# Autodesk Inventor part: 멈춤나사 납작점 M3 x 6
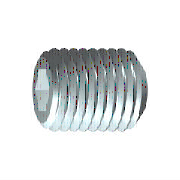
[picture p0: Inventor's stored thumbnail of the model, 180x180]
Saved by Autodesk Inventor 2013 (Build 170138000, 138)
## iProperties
IsCustomPart: 1
Created: 2012-02
Part Number: 멈춤나사 납작점 M3 x 6
Material: 강철, 연강
Description: 6각 소켓 머리 없는 멈춤 나사
Document SubType Name: Modeling
Standard: KS B 1028
Designer: mduedu
Standards Organization: KS
Language: ko-KR
Size Designation: 납작점M3x6
Categories: <MemberInstance><Categories><Category DisplayName="조임쇠" InternalName="e4da775c-781d-43d5-af7c-5136215cf5a6" Mnemonic="FSTN"><Category DisplayName="볼트" InternalN
Density: 1 g/cm^3
Author: mduedu
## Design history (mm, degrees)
sketch "스케치1"
  geometry: L1 (0, 0)-(3.5, 0); L2 (6, 0.866)-(6, 1.5); L3 (6, 1.5)-(0, 1.5); L4 (6, 0.866)-(4, 0.866); L5 (4, 0.866)-(3.5, 0); L6 (0, -0.3)-(0, 1.8) reference; L7 (0, 1.5)-(0, 0)
  constraints: 13 end point, 3 parallel, 1 collinear, 1 perpendicular, 1 point on line
  dimensions: "d0" = 2 distance of L2.start L4.end (= INTI); "d1" = 60 deg angle of L5 L1; "d2" = 3 diameter of L3 L1 (= NND); "d3" = 1.73205 diameter of L4 L1 (= 1.1547 x SW); "d5" = 6 distance from line of L2 L3.end (= NLG)
revolve "본체" sketch "스케치1" stored, may be unused: angle "d6" = 90 deg
sketch "스케치2"
  geometry: L1 (-0.433, 0.75)-(0.433, 0.75); L2 (0.433, 0.75)-(0.866, 0); L3 (0.866, 0)-(0.433, -0.75); L4 (0.433, -0.75)-(-0.433, -0.75); L5 (-0.433, -0.75)-(-0.866, 0); L6 (-0.866, 0)-(-0.433, 0.75); A1 r 0.866 centre (0, 0) between (-0.433, 0.75) and (0.433, 0.75) reference; 2 further points
  constraints: 12 end point, 2 point on circle, 1 coincident, 1 horizontal, 11 other
extrude "슬롯" join sketch "스케치2" taper "d9" = 0 deg; stored distance "d21" = 10
workaxis "Work Axis1"
workplane "Work Plane1"
body "Solid1"
chamfer "모따기1" distance "d7" = 0.30673 (= -0.5 x GD1 + 0.5 x NND); stored, may be unused: angle "d8" = 45 deg (= FAWI), second distance "d29" = 0.30673 (= -0.5 x GD1 + 0.5 x NND)
feature "스레드" dims "d11" = 6 (= NLG), "d12" = 0
chamfer "모따기2" distance "d13" = 0.30673 (= -0.5 x GD1 + 0.5 x NND); stored, may be unused: angle "d14" = 45 deg (= FAWI), second distance "d30" = 0.30673 (= -0.5 x GD1 + 0.5 x NND)
other parameters: "NND" = 3 [user parameter; used in 5 equation terms], "NLG" = 6 [user parameter; used in 2 equation terms], "INTI" = 2 [user parameter; used in 1 equation term], "FAWI" = 45 deg [user parameter; used in 2 equation terms], "SW" = 1.5 [user parameter; used in 2 equation terms], "GD1" = 2.38655 (= THREADDIA - 1.2269 x PTC) [user parameter; used in 4 equation terms], "d4" = 0, "FAWI1" = 45 deg [user parameter], "d15" = 0, "d31" = 0, "GUL" = 0.30673 (= 0.61345 x PTC) [user parameter], "SPD" = 2 [user parameter], "TOA" = 30 deg [user parameter], "THREADDIA" = 3 [user parameter; used in 1 equation term], "PTC" = 0.5 [user parameter; used in 4 equation terms], "GAL" = 0.30673 (= 0.61345 x PTC) [user parameter], "E0" = 1.7325 (= 1.155 x SW) [user parameter]
